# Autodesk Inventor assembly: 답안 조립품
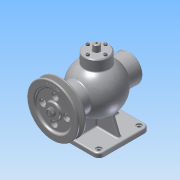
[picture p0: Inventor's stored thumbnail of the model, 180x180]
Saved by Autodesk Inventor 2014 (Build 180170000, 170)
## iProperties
Created: 2017-01
Part Number: 답안 조립품
Document SubType Name: Assembly
Designer: ksu
Author: ksu
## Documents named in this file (17)
- C:\Users\ksu\Desktop\470118V1016\답안 조립품.iam
- C:\Users\ksu\Desktop\470118V1016\1 본체.ipt
- C:\Users\ksu\Desktop\470118V1016\V-벨트풀리.ipt
- C:\Users\ksu\Desktop\470118V1016\너트 M8.ipt
- C:\Users\ksu\Desktop\470118V1016\뒤커버.ipt
- C:\Users\ksu\Desktop\470118V1016\멈춤링- 15 x 1.ipt
- C:\Users\ksu\Desktop\470118V1016\멈춤링- 35x1.6.ipt
- C:\Users\ksu\Desktop\470118V1016\베어링- 6202.ipt
- C:\Users\ksu\Desktop\470118V1016\볼트 M4 x 12.ipt
- C:\Users\ksu\Desktop\470118V1016\볼트 M4 x 16.ipt
- C:\Users\ksu\Desktop\470118V1016\부시.ipt
- C:\Users\ksu\Desktop\470118V1016\상부커버.ipt
- C:\Users\ksu\Desktop\470118V1016\슬라이드.ipt
- C:\Users\ksu\Desktop\470118V1016\앞커버.ipt
- C:\Users\ksu\Desktop\470118V1016\오일실 15 30 7.ipt
- C:\Users\ksu\Desktop\470118V1016\키 4 x 4 x 12.ipt
- C:\Users\ksu\Desktop\470118V1016\편심축.ipt
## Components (17 placed, 6 different names)
1. 1 본체:1 — Mate:1, Mate:2, Mate:3, Mate:17, Mate:18, Mate:19, Mate:48, Mate:49, Mate:51
2. V-벨트풀리:1 — Mate:42, Mate:43, Mate:44, Mate:45, Mate:47
3. KS B 1336 - 35x1.6:1 — Mate:40, Mate:41
4. KS B 2023 - 6202 - 15 x 35 x 11 - 7.8:1 — Mate:30, Mate:33, Mate:34, Mate:35
5. KS B 1021 - 에 따름 ISO 1207 - 미터 A  M 4 x 12:1 — Mate:53, Mate:58
6. ISO 4762 M4 x 16:1 — Mate:4, Mate:5
7. ISO 4762 M4 x 16:2 — Mate:10, Mate:11
8. ISO 4762 M4 x 16:3 — Mate:8, Mate:9
9. ISO 4762 M4 x 16:4 — Mate:6, Mate:7
10. ISO 4762 M4 x 16:5 — Mate:20, Mate:21
11. ISO 4762 M4 x 16:6 — Mate:22, Mate:23
12. ISO 4762 M4 x 16:7 — Mate:26, Mate:27
13. ISO 4762 M4 x 16:8 — Mate:24, Mate:25
14. KS B 2023 - 6202 - 15 x 35 x 11 - 7.8:2 — Mate:31, Mate:32, Mate:39, Mate:41
15. KS B 1021 - 에 따름 ISO 1207 - 미터 A  M 4 x 12:2 — Mate:52, Mate:59
16. KS B 1021 - 에 따름 ISO 1207 - 미터 A  M 4 x 12:3 — Mate:54, Mate:56
17. KS B 1021 - 에 따름 ISO 1207 - 미터 A  M 4 x 12:4 — Mate:55, Mate:57
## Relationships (47: Mate 47)
- Mate:1: 1 본체:1
- Mate:2: 1 본체:1
- Mate:3: 1 본체:1
- Mate:4: ISO 4762 M4 x 16:1
- Mate:5: ISO 4762 M4 x 16:1
- Mate:6: ISO 4762 M4 x 16:4
- Mate:7: ISO 4762 M4 x 16:4
- Mate:8: ISO 4762 M4 x 16:3
- Mate:9: ISO 4762 M4 x 16:3
- Mate:10: ISO 4762 M4 x 16:2
- Mate:11: ISO 4762 M4 x 16:2
- Mate:17: 1 본체:1
- Mate:18: 1 본체:1
- Mate:19: 1 본체:1
- Mate:20: ISO 4762 M4 x 16:5
- Mate:21: ISO 4762 M4 x 16:5
- Mate:22: ISO 4762 M4 x 16:6
- Mate:23: ISO 4762 M4 x 16:6
- Mate:24: ISO 4762 M4 x 16:8
- Mate:25: ISO 4762 M4 x 16:8
- Mate:26: ISO 4762 M4 x 16:7
- Mate:27: ISO 4762 M4 x 16:7
- Mate:30: KS B 2023 - 6202 - 15 x 35 x 11 - 7.8:1
- Mate:31: KS B 2023 - 6202 - 15 x 35 x 11 - 7.8:2
- Mate:32: KS B 2023 - 6202 - 15 x 35 x 11 - 7.8:2
- Mate:33: KS B 2023 - 6202 - 15 x 35 x 11 - 7.8:1
- Mate:34: KS B 2023 - 6202 - 15 x 35 x 11 - 7.8:1
- Mate:35: KS B 2023 - 6202 - 15 x 35 x 11 - 7.8:1
- Mate:39: KS B 2023 - 6202 - 15 x 35 x 11 - 7.8:2
- Mate:40: KS B 1336 - 35x1.6:1
- Mate:41: KS B 1336 - 35x1.6:1 ↔ KS B 2023 - 6202 - 15 x 35 x 11 - 7.8:2
- Mate:42: V-벨트풀리:1
- Mate:43: V-벨트풀리:1
- Mate:44: V-벨트풀리:1
- Mate:45: V-벨트풀리:1
- Mate:47: V-벨트풀리:1
- Mate:48: 1 본체:1
- Mate:49: 1 본체:1
- Mate:51: 1 본체:1
- Mate:52: KS B 1021 - 에 따름 ISO 1207 - 미터 A  M 4 x 12:2
- Mate:53: KS B 1021 - 에 따름 ISO 1207 - 미터 A  M 4 x 12:1
- Mate:54: KS B 1021 - 에 따름 ISO 1207 - 미터 A  M 4 x 12:3
- Mate:55: KS B 1021 - 에 따름 ISO 1207 - 미터 A  M 4 x 12:4
- Mate:56: KS B 1021 - 에 따름 ISO 1207 - 미터 A  M 4 x 12:3
- Mate:57: KS B 1021 - 에 따름 ISO 1207 - 미터 A  M 4 x 12:4
- Mate:58: KS B 1021 - 에 따름 ISO 1207 - 미터 A  M 4 x 12:1
- Mate:59: KS B 1021 - 에 따름 ISO 1207 - 미터 A  M 4 x 12:2
